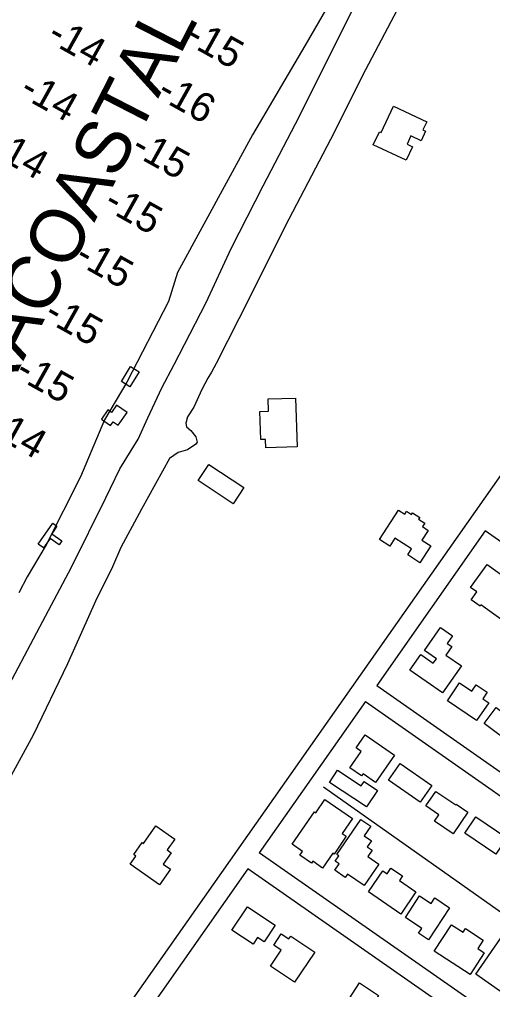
# Model space of a CAD drawing. Extents: x 3683402 to 3721514, y 487807 to 513565.
# Drawn here: x 3699177 to 3699909, y 497379 to 498879 of the extents above; entities that cross this region are included whole.
import ezdxf

# ---------------------------------------------------------------- set-up
doc = ezdxf.new("R2010")
doc.units = 0
for name, color, linetype in [('V-BLDG-OTLN', 7, 'Continuous'), ('V-CHAN-DOCK', 7, 'Continuous'), ('V-LEVE-TOET', 7, 'Continuous'), ('V-RIVR-IDEN', 7, 'Continuous'), ('V-ROAD-CNTR', 7, 'Continuous'), ('V-TOPO-SHOR', 7, 'Continuous'), ('V-TOPO-SPOT', 7, 'Continuous')]:
    doc.layers.add(name, color=color, linetype=linetype)

msp = doc.modelspace()

# ---------------------------------------------------------------- linework, layer by layer
at = {"layer": 'V-BLDG-OTLN'}
for points in [[(3699755.6, 498745), (3699806.9, 498720.8), (3699801, 498708.5), (3699805.2, 498706.5), (3699798.2, 498691.6), (3699782.5, 498699), (3699776.4, 498686), (3699784.7, 498682.1), (3699775, 498661.5), (3699724.2, 498685.4), (3699733.6, 498705.5), (3699736.4, 498704.2)], [(3699604.1, 498293.8), (3699606.6, 498218.5), (3699557.9, 498216.9), (3699557.5, 498229.8), (3699550.4, 498229.6), (3699548.9, 498272.8), (3699562.3, 498273.3), (3699561.6, 498292.4)], [(3699453.2, 498166.2), (3699469.7, 498191.2), (3699524.1, 498155.3), (3699507.6, 498130.3)], [(3699763, 498120.5), (3699772.8, 498114.2), (3699775.7, 498118.7), (3699783.1, 498113.9), (3699784.8, 498116.5), (3699796, 498109.3), (3699794.3, 498106.6), (3699803.8, 498100.5), (3699800.3, 498095), (3699809.1, 498089.3), (3699799.3, 498074.1), (3699813, 498065.3), (3699796.2, 498039.2), (3699777.4, 498051.4), (3699783.3, 498060.5), (3699757.4, 498077.2), (3699749.6, 498065), (3699733.8, 498075.1)], [(3699947.3, 497932.6), (3699934.2, 497942.1), (3699934.4, 497942.5), (3699890.8, 497974), (3699889.5, 497972.2), (3699875.8, 497982.1), (3699884.5, 497994.2), (3699874.7, 498001.2), (3699900.4, 498036.7), (3699968.3, 497987.6), (3699958.2, 497973.6), (3699970.5, 497964.7)], [(3699860.4, 497879.8), (3699831.1, 497838.1), (3699781, 497873.3), (3699797.9, 497897.3), (3699817, 497883.8), (3699821.9, 497890.7), (3699803.5, 497903.6), (3699828.4, 497939.1), (3699846.9, 497926.1), (3699838.6, 497914.4), (3699845.6, 497909.5), (3699836.5, 497896.5)], [(3699884, 497795.3), (3699838.9, 497825.9), (3699857.7, 497853.4), (3699876.6, 497840.5), (3699883.5, 497850.6), (3699900.5, 497839), (3699893.7, 497829), (3699902.7, 497822.9)], [(3699895.6, 497790.6), (3699914.2, 497815.5), (3699961.3, 497780.3), (3699942.8, 497755.5)], [(3699727.8, 497699.4), (3699708.4, 497712.9), (3699706.2, 497709.8), (3699688.1, 497722.3), (3699705.6, 497747.6), (3699697.8, 497753), (3699711.6, 497773), (3699757, 497741.7)], [(3699713.6, 497661.7), (3699656.4, 497699.7), (3699669, 497718.7), (3699705.5, 497694.4), (3699710, 497701.1), (3699730.6, 497687.4)], [(3699796.6, 497668.9), (3699747.6, 497703.1), (3699765.6, 497729), (3699814.7, 497694.8)], [(3699645.7, 497567.3), (3699630.5, 497577.7), (3699628.6, 497574.9), (3699610.8, 497587.1), (3699614.9, 497593.1), (3699598.9, 497604), (3699633.1, 497654.2), (3699635.4, 497652.7), (3699649.4, 497673.2), (3699692, 497644.1), (3699676.1, 497620.8), (3699682.3, 497616.5), (3699663.5, 497589), (3699661.5, 497590.4)], [(3699847.6, 497620.3), (3699818.7, 497639.8), (3699825.4, 497649.8), (3699805.6, 497663.2), (3699820.9, 497685.8), (3699851.8, 497664.9), (3699852.5, 497665.9), (3699870.3, 497653.8)], [(3699710, 497540.4), (3699684.6, 497558), (3699681, 497552.9), (3699664.9, 497564), (3699671.7, 497573.8), (3699665.4, 497578.1), (3699671, 497586.2), (3699667.8, 497588.4), (3699705.2, 497642.5), (3699720.5, 497631.9), (3699710.3, 497617.1), (3699721.5, 497609.4), (3699715, 497600.1), (3699722.6, 497594.8), (3699715.8, 497585), (3699732.7, 497573.2)], [(3699913.5, 497589), (3699866, 497621.1), (3699883, 497646.3), (3699930.5, 497614.2)], [(3699393.4, 497541.3), (3699348.2, 497573.3), (3699357.1, 497585.8), (3699353.8, 497588.1), (3699366.9, 497606.6), (3699368.8, 497605.3), (3699388, 497632.4), (3699417.1, 497611.8), (3699405.4, 497595.4), (3699411.7, 497590.9), (3699399.4, 497573.5), (3699410.6, 497565.5)], [(3699766.7, 497496.2), (3699717, 497530.3), (3699739.2, 497562.8), (3699745.5, 497558.5), (3699751.5, 497567.3), (3699769.4, 497555), (3699764.6, 497548), (3699790.2, 497530.5)], [(3699773.9, 497490.8), (3699795.9, 497524.1), (3699813.6, 497512.4), (3699819.2, 497521), (3699842.1, 497505.9), (3699809.5, 497456.5), (3699794.2, 497466.5), (3699799.2, 497474.1)], [(3699505.6, 497471.1), (3699529.6, 497507.4), (3699572.5, 497479), (3699555.5, 497453.3), (3699545.2, 497460.1), (3699538.3, 497449.5)], [(3699873.9, 497402.6), (3699818.5, 497438.6), (3699845.3, 497479.7), (3699863.1, 497468.1), (3699866.6, 497473.6), (3699894.1, 497455.7), (3699885.8, 497442.9), (3699895.9, 497436.4)], [(3699602.6, 497390.8), (3699565.5, 497415.5), (3699582, 497440.3), (3699570.2, 497448.2), (3699581.9, 497465.8), (3699593.7, 497458), (3699596.6, 497462.2), (3699633.7, 497437.5)], [(3699882.6, 497403.4), (3699920.8, 497458.3), (3699949, 497438.7), (3699940.5, 497426.4), (3699956, 497415.6), (3699926.3, 497372.9)], [(3699702.8, 497389.6), (3699732.2, 497370.3), (3699727.2, 497362.6), (3699745.3, 497350.7), (3699725.9, 497321.1), (3699692.2, 497343.2), (3699695, 497347.4), (3699681.1, 497356.6)]]:
    msp.add_lwpolyline(points, close=True, dxfattribs=at)
at = {"layer": 'V-CHAN-DOCK'}
for points in [[(3699348, 498311), (3699334.6, 498319.2), (3699348.8, 498342.4), (3699362.2, 498334.2), (3699348, 498311)], [(3699343.4, 498271.5), (3699327.2, 498282.7), (3699319.4, 498271.5), (3699313.8, 498275.4), (3699304, 498261.4), (3699318, 498251.6), (3699321.9, 498257.1), (3699329.6, 498251.8), (3699343.4, 498271.5)], [(3699238.3, 498067), (3699224.3, 498076.8), (3699214.1, 498062.1), (3699205.9, 498067.8), (3699228.5, 498100.2), (3699235, 498095.7), (3699226.9, 498084.1), (3699242.6, 498073.2), (3699238.3, 498067)]]:
    msp.add_lwpolyline(points, dxfattribs=at)
at = {"layer": 'V-LEVE-TOET'}
for points in [[(3699155.8, 497840.7), (3699208.6, 497940.2), (3699257.5, 498032.5), (3699310.7, 498139.4), (3699332.5, 498184.2), (3699360.6, 498230.1), (3699375.5, 498263.3), (3699397.3, 498309.7), (3699416.2, 498345.8), (3699432.1, 498376.5), (3699466, 498441.4), (3699504.2, 498524.9), (3699554.1, 498622), (3699610.2, 498729.3), (3699674.5, 498858.6), (3699745.7, 499000.2)], [(3699795.1, 498958.6), (3699712.3, 498800.9), (3699658.1, 498693.6), (3699593.7, 498570.1), (3699516.3, 498416.4), (3699481, 498347.1), (3699474.2, 498333.9), (3699468.4, 498324.6), (3699459.2, 498307.1), (3699446.7, 498279.7), (3699437, 498264.6), (3699434.6, 498254.9), (3699435.6, 498249.5), (3699441.9, 498243.7), (3699449.7, 498234), (3699451.7, 498225.7), (3699449.8, 498222.3), (3699437.1, 498214), (3699422.5, 498209.5), (3699408.9, 498200.2), (3699365.8, 498122.1), (3699333.9, 498062.6), (3699320.8, 498032.8), (3699294.7, 497979.6), (3699251.2, 497883), (3699198.5, 497772.8), (3699129.3, 497646.8)]]:
    msp.add_lwpolyline(points, dxfattribs=at)
at = {"layer": 'V-ROAD-CNTR'}
for points in [[(3700937.9, 499631.9), (3699922.2, 498175.6), (3699164.4, 497097.7)], [(3699897.5, 498088.4), (3699729.5, 497849.4)], [(3700699.3, 497528.1), (3699897.5, 498088.4)], [(3699729.5, 497849.4), (3700530.6, 497288.9)], [(3699712.2, 497824.8), (3699547.5, 497590.6)], [(3699712.2, 497824.8), (3700513.4, 497264.3)], [(3700349.6, 497031.3), (3699547.5, 497590.6)], [(3699530.3, 497566), (3699362, 497326.6)], [(3700332.5, 497006.7), (3699530.3, 497566)]]:
    msp.add_lwpolyline(points, dxfattribs=at)
at = {"layer": 'V-TOPO-SHOR'}
for points in [[(3699892.1, 499384), (3699869, 499316.6), (3699822.8, 499219.4), (3699712.2, 499000.3), (3699618.3, 498838.2), (3699537.2, 498700.8), (3699421.5, 498488.1), (3699407.4, 498442.8), (3699343.2, 498318.3), (3699308.4, 498260), (3699271.2, 498171.8), (3699218.5, 498066.8), (3699188.9, 498017.5), (3699176.2, 497992.9)], [(3699647.3, 497692.9), (3700075.1, 497391.1), (3700412.4, 497150.5), (3700405.5, 497144.7)]]:
    msp.add_lwpolyline(points, dxfattribs=at)

# ---------------------------------------------------------------- texts
at = {"layer": 'V-RIVR-IDEN'}
msp.add_text('INTRACOASTAL', height=83, rotation=62.818, dxfattribs=at).set_placement((3699064.6, 498120))
at = {"layer": 'V-TOPO-SPOT'}
for s, p in [('-14', (3699217.7, 498846.2)), ('-15', (3699431, 498843.6)), ('-14', (3699175, 498761.7)), ('-16', (3699387.4, 498758.9)), ('-14', (3699129.1, 498672.4)), ('-15', (3699347.4, 498672.6)), ('-15', (3699305.1, 498587.4)), ('-15', (3699260.3, 498503.9)), ('-15', (3699212.8, 498415.3)), ('-15', (3699168.2, 498326.5)), ('-14', (3699126.5, 498240.7))]:
    msp.add_text(s, height=45, rotation=330.7933, dxfattribs=at).set_placement(p)

doc.saveas('drawing.dxf')
